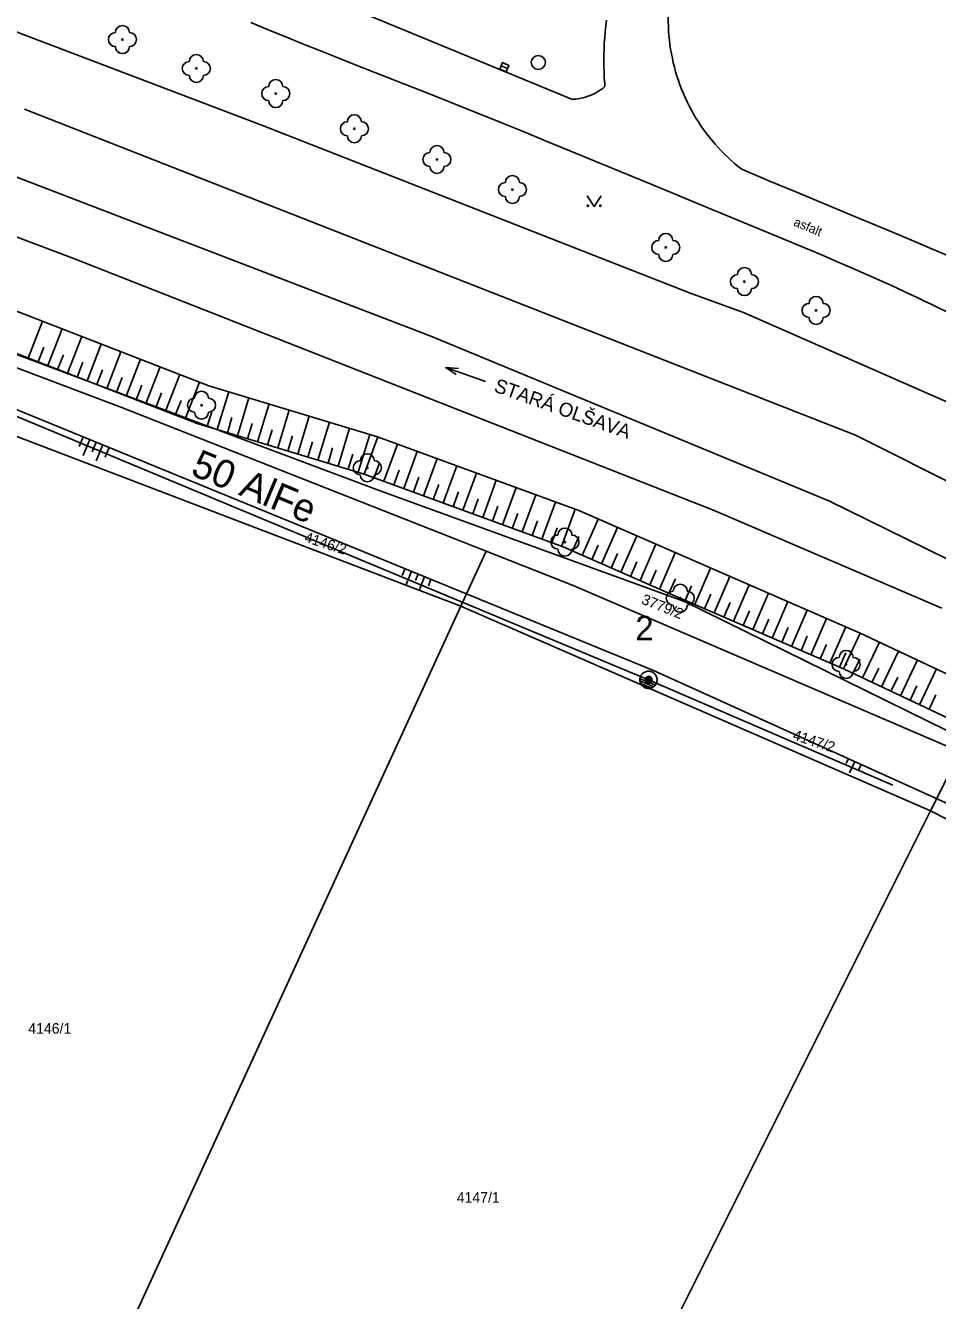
# Model space of a CAD drawing. Extents: x -540150 to -533593, y -1185082 to -1180066.
# Drawn here: x -536338.1 to -536273, y -1184826.1 to -1184735.2 of the extents above; entities that cross this region are included whole.
import ezdxf

# ---------------------------------------------------------------- set-up
doc = ezdxf.new("R2010")
doc.units = 0
for name, color, linetype in [('KN_HRAN_K_Ú', 7, 'Continuous'), ('KN_HRAN_PARCEL', 7, 'Continuous'), ('KN_PARC_Č', 7, 'Continuous'), ('Vrstva 10', 7, 'Continuous'), ('Vrstva 13', 7, 'Continuous'), ('Vrstva 14', 7, 'Continuous'), ('Vrstva 15', 7, 'Continuous'), ('Vrstva 2', 7, 'Continuous'), ('Vrstva 22', 7, 'Continuous'), ('Vrstva 25', 7, 'Continuous'), ('Vrstva 27', 7, 'Continuous'), ('Vrstva 36', 7, 'Continuous'), ('Vrstva 40', 7, 'Continuous'), ('Vrstva 45', 7, 'Continuous'), ('Vrstva 52', 7, 'Continuous'), ('Vrstva 53', 7, 'Continuous'), ('Vrstva 7', 7, 'Continuous')]:
    doc.layers.add(name, color=color, linetype=linetype)

# ---------------------------------------------------------------- blocks, each defined once
blk = doc.blocks.new('VN440')
at = {"layer": 'Vrstva 2'}
for points in [[(1.22, 0), (1.21, 0.13), (1.19, 0.25), (1.16, 0.38), (1.11, 0.5), (1.05, 0.61), (0.98, 0.72), (0.9, 0.82), (0.81, 0.91), (0.71, 0.99), (0.6, 1.06), (0.49, 1.12), (0.37, 1.16), (0.25, 1.2), (0.12, 1.22), (-0.01, 1.22), (-0.14, 1.22), (-0.26, 1.2), (-0.39, 1.16), (-0.51, 1.12), (-0.62, 1.06), (-0.73, 0.99), (-0.83, 0.91), (-0.92, 0.82), (-1, 0.72), (-1.07, 0.61), (-1.13, 0.5), (-1.18, 0.38), (-1.21, 0.25), (-1.23, 0.13), (-1.24, 0), (-1.23, -0.13), (-1.21, -0.26), (-1.18, -0.38), (-1.13, -0.5), (-1.07, -0.62), (-1, -0.73), (-0.92, -0.83), (-0.83, -0.92), (-0.73, -1), (-0.62, -1.07), (-0.51, -1.13), (-0.39, -1.17), (-0.26, -1.2), (-0.14, -1.23), (-0.01, -1.23), (0.12, -1.23), (0.25, -1.2), (0.37, -1.17), (0.49, -1.13), (0.6, -1.07), (0.71, -1), (0.81, -0.92), (0.9, -0.83), (0.98, -0.73), (1.05, -0.62), (1.11, -0.5), (1.16, -0.38), (1.19, -0.26), (1.21, -0.13), (1.22, 0)], [(-1.24, 0), (1.22, 0)], [(-1.18, -0.34), (1.1, -0.34)], [(-1.01, -0.63), (0.97, -0.63)], [(-0.74, -0.92), (0.68, -0.92)]]:
    blk.add_lwpolyline(points, dxfattribs=at)

msp = doc.modelspace()

# ---------------------------------------------------------------- linework, layer by layer
at = {"layer": 'KN_HRAN_K_Ú'}
for p, q in [((-536356.012, -1184743.741), (-536334.692, -1184751.821)), ((-536334.692, -1184751.821), (-536288.932, -1184769.811)), ((-536288.932, -1184769.811), (-536272.712, -1184776.781))]:
    msp.add_line(p, q, dxfattribs=at)
at = {"layer": 'KN_HRAN_PARCEL'}
for p, q in [((-536309.152, -1184757.381), (-536365.022, -1184735.941)), ((-536278.862, -1184764.441), (-536338.122, -1184741.201)), ((-536375.042, -1184745.111), (-536312.562, -1184768.481)), ((-536280.772, -1184769.131), (-536309.152, -1184757.381)), ((-536339.442, -1184759.351), (-536331.262, -1184762.451)), ((-536331.262, -1184762.451), (-536305.212, -1184772.721)), ((-536341.152, -1184763.591), (-536307.012, -1184776.641)), ((-536244.672, -1184781.561), (-536278.862, -1184764.441)), ((-536312.562, -1184768.481), (-536291.062, -1184776.301)), ((-536249.882, -1184784.311), (-536280.772, -1184769.131)), ((-536307.012, -1184776.641), (-536305.212, -1184772.721)), ((-536305.212, -1184772.721), (-536298.992, -1184775.171)), ((-536298.992, -1184775.171), (-536271.392, -1184787.031)), ((-536337.992, -1184844.061), (-536307.012, -1184776.641)), ((-536307.012, -1184776.641), (-536273.502, -1184791.241)), ((-536291.062, -1184776.301), (-536256.302, -1184793.401)), ((-536273.502, -1184791.241), (-536271.392, -1184787.031)), ((-536306.452, -1184857.041), (-536273.502, -1184791.241)), ((-536273.502, -1184791.241), (-536252.972, -1184801.691))]:
    msp.add_line(p, q, dxfattribs=at)
at = {"layer": 'Vrstva 10'}
for p, q in [((-536311.657, -1184735.296), (-536324.262, -1184730.101)), ((-536299.052, -1184740.491), (-536311.657, -1184735.296)), ((-536285.045, -1184746.291), (-536286.972, -1184745.481)), ((-536285.075, -1184750.004), (-536290.122, -1184747.921)), ((-536293.262, -1184781.211), (-536349.102, -1184758.351)), ((-536257.372, -1184797.481), (-536293.262, -1184781.211))]:
    msp.add_line(p, q, dxfattribs=at)
for points in [[(-536291.989, -1184737.241), (-536292.044, -1184736.917), (-536292.092, -1184736.592), (-536292.132, -1184736.265), (-536292.164, -1184735.938), (-536292.187, -1184735.61), (-536292.203, -1184735.282), (-536292.211, -1184734.953), (-536292.211, -1184734.624), (-536292.203, -1184734.296), (-536292.187, -1184733.967), (-536292.162, -1184733.639), (-536292.13, -1184733.312), (-536292.09, -1184732.986), (-536292.042, -1184732.66), (-536291.986, -1184732.336), (-536291.923, -1184732.014), (-536291.851, -1184731.693), (-536291.772, -1184731.374), (-536291.684, -1184731.057), (-536291.59, -1184730.742), (-536291.487, -1184730.429), (-536291.432, -1184730.271)], [(-536318.292, -1184736.521), (-536319.2, -1184736.153), (-536320.787, -1184735.503), (-536321.976, -1184735.011)], [(-536296.617, -1184734.851), (-536296.669, -1184735.259), (-536296.713, -1184735.667), (-536296.749, -1184736.077), (-536296.777, -1184736.487)], [(-536309.01, -1184740.205), (-536313.153, -1184738.57), (-536314.707, -1184737.955), (-536316.065, -1184737.414), (-536317.253, -1184736.939), (-536318.292, -1184736.521)], [(-536296.777, -1184736.487), (-536296.798, -1184736.898), (-536296.81, -1184737.309), (-536296.814, -1184737.72), (-536296.81, -1184738.132), (-536296.798, -1184738.543), (-536296.778, -1184738.953), (-536296.75, -1184739.364), (-536296.732, -1184739.581)], [(-536286.972, -1184745.481), (-536287.229, -1184745.277), (-536287.482, -1184745.066), (-536287.729, -1184744.849), (-536287.971, -1184744.626), (-536288.208, -1184744.398), (-536288.438, -1184744.164), (-536288.663, -1184743.924), (-536288.882, -1184743.679), (-536289.096, -1184743.428), (-536289.302, -1184743.173), (-536289.503, -1184742.912), (-536289.697, -1184742.647), (-536289.885, -1184742.377), (-536290.066, -1184742.103), (-536290.241, -1184741.824), (-536290.408, -1184741.541), (-536290.569, -1184741.254), (-536290.722, -1184740.963), (-536290.869, -1184740.669), (-536291.008, -1184740.371), (-536291.14, -1184740.07), (-536291.265, -1184739.766), (-536291.382, -1184739.459), (-536291.492, -1184739.149), (-536291.594, -1184738.836), (-536291.688, -1184738.521), (-536291.775, -1184738.204), (-536291.854, -1184737.885), (-536291.925, -1184737.564), (-536291.989, -1184737.241)], [(-536296.732, -1184739.581), (-536296.869, -1184739.692), (-536297.011, -1184739.796), (-536297.158, -1184739.893), (-536297.309, -1184739.984), (-536297.464, -1184740.068), (-536297.622, -1184740.145), (-536297.784, -1184740.214), (-536297.949, -1184740.276), (-536298.116, -1184740.331), (-536298.286, -1184740.378), (-536298.458, -1184740.417), (-536298.631, -1184740.448), (-536298.806, -1184740.472), (-536298.981, -1184740.487), (-536299.052, -1184740.491)], [(-536305.383, -1184741.646), (-536306.644, -1184741.143), (-536309.01, -1184740.205)], [(-536296.971, -1184745.087), (-536301.082, -1184743.391), (-536302.607, -1184742.766), (-536304.039, -1184742.186), (-536305.383, -1184741.646)], [(-536290.122, -1184747.921), (-536292.861, -1184746.786), (-536296.971, -1184745.087)], [(-536276.681, -1184749.772), (-536279.254, -1184748.7), (-536283.116, -1184747.096), (-536285.045, -1184746.291)], [(-536268.452, -1184753.311), (-536269.601, -1184752.801), (-536270.679, -1184752.329), (-536271.692, -1184751.889), (-536272.644, -1184751.48), (-536273.536, -1184751.098), (-536275.212, -1184750.389), (-536276.681, -1184749.772)], [(-536281.34, -1184751.564), (-536282.435, -1184751.103), (-536283.394, -1184750.701), (-536285.075, -1184750.004)], [(-536272.343, -1184755.642), (-536272.888, -1184755.375), (-536273.416, -1184755.119), (-536273.929, -1184754.873), (-536274.427, -1184754.637), (-536275.395, -1184754.186), (-536276.304, -1184753.769), (-536277.159, -1184753.383), (-536277.962, -1184753.025), (-536278.717, -1184752.693), (-536279.425, -1184752.385), (-536280.09, -1184752.098), (-536281.34, -1184751.564)]]:
    msp.add_lwpolyline(points, dxfattribs=at)
at = {"layer": 'Vrstva 14'}
for p, q in [((-536364.873, -1184745.447), (-536324.985, -1184760.916)), ((-536365.832, -1184748.091), (-536325.812, -1184763.611)), ((-536324.985, -1184760.916), (-536312.943, -1184764.556)), ((-536325.812, -1184763.611), (-536313.902, -1184767.211)), ((-536312.943, -1184764.556), (-536298.603, -1184769.815)), ((-536313.902, -1184767.211), (-536299.722, -1184772.411)), ((-536298.603, -1184769.815), (-536290.426, -1184773.389)), ((-536299.722, -1184772.411), (-536291.692, -1184775.921)), ((-536290.426, -1184773.389), (-536278.525, -1184778.549)), ((-536291.692, -1184775.921), (-536279.722, -1184781.111)), ((-536278.525, -1184778.549), (-536265.708, -1184784.588)), ((-536279.722, -1184781.111), (-536267.072, -1184787.071))]:
    msp.add_line(p, q, dxfattribs=at)
at = {"layer": 'Vrstva 15'}
for p, q in [((-536337.862, -1184758.938), (-536336.845, -1184756.317)), ((-536336.463, -1184759.48), (-536335.446, -1184756.859)), ((-536335.065, -1184760.023), (-536334.048, -1184757.401)), ((-536333.666, -1184760.565), (-536332.649, -1184757.944)), ((-536337.162, -1184759.209), (-536336.756, -1184758.161)), ((-536335.764, -1184759.752), (-536335.357, -1184758.703)), ((-536332.268, -1184761.107), (-536331.251, -1184758.486)), ((-536334.365, -1184760.294), (-536333.959, -1184759.245)), ((-536332.967, -1184760.836), (-536332.56, -1184759.788)), ((-536330.869, -1184761.65), (-536329.852, -1184759.028)), ((-536329.471, -1184762.192), (-536328.454, -1184759.571)), ((-536331.568, -1184761.379), (-536331.162, -1184760.33)), ((-536328.072, -1184762.735), (-536327.055, -1184760.113)), ((-536326.673, -1184763.277), (-536325.657, -1184760.655)), ((-536330.17, -1184761.921), (-536329.763, -1184760.872)), ((-536328.771, -1184762.463), (-536328.365, -1184761.415)), ((-536324.376, -1184764.045), (-536323.56, -1184761.347)), ((-536327.373, -1184763.006), (-536326.966, -1184761.957)), ((-536322.94, -1184764.479), (-536322.124, -1184761.781)), ((-536321.504, -1184764.913), (-536320.689, -1184762.215)), ((-536325.094, -1184763.828), (-536324.768, -1184762.749)), ((-536323.658, -1184764.262), (-536323.332, -1184763.183)), ((-536320.069, -1184765.347), (-536319.253, -1184762.649)), ((-536318.633, -1184765.781), (-536317.817, -1184763.083)), ((-536317.197, -1184766.215), (-536316.381, -1184763.517)), ((-536322.222, -1184764.696), (-536321.896, -1184763.617)), ((-536320.787, -1184765.13), (-536320.46, -1184764.051)), ((-536315.761, -1184766.649), (-536314.945, -1184763.951)), ((-536314.325, -1184767.083), (-536313.509, -1184764.385)), ((-536333.936, -1184764.56), (-536334.219, -1184765.245)), ((-536333.473, -1184764.749), (-536333.949, -1184765.898)), ((-536333.01, -1184764.939), (-536333.296, -1184765.628)), ((-536332.547, -1184765.128), (-536333.025, -1184766.281)), ((-536332.084, -1184765.318), (-536332.372, -1184766.011)), ((-536319.351, -1184765.564), (-536319.025, -1184764.485)), ((-536317.915, -1184765.998), (-536317.589, -1184764.919)), ((-536316.479, -1184766.432), (-536316.153, -1184765.353)), ((-536313.902, -1184767.211), (-536312.93, -1184764.561)), ((-536312.494, -1184767.727), (-536311.522, -1184765.077)), ((-536315.043, -1184766.866), (-536314.717, -1184765.787)), ((-536311.085, -1184768.244), (-536310.114, -1184765.594)), ((-536309.677, -1184768.76), (-536308.706, -1184766.11)), ((-536313.198, -1184767.469), (-536312.809, -1184766.409)), ((-536311.79, -1184767.986), (-536311.401, -1184766.926)), ((-536308.269, -1184769.277), (-536307.297, -1184766.627)), ((-536306.861, -1184769.793), (-536305.889, -1184767.143)), ((-536310.381, -1184768.502), (-536309.993, -1184767.442)), ((-536308.973, -1184769.019), (-536308.584, -1184767.958)), ((-536305.452, -1184770.31), (-536304.481, -1184767.659)), ((-536307.565, -1184769.535), (-536307.176, -1184768.475)), ((-536306.156, -1184770.051), (-536305.768, -1184768.991)), ((-536304.044, -1184770.826), (-536303.072, -1184768.176)), ((-536302.636, -1184771.343), (-536301.664, -1184768.693)), ((-536304.748, -1184770.568), (-536304.359, -1184769.508)), ((-536301.227, -1184771.859), (-536300.256, -1184769.209)), ((-536299.819, -1184772.375), (-536298.848, -1184769.725)), ((-536303.34, -1184771.084), (-536302.951, -1184770.024)), ((-536301.932, -1184771.601), (-536301.543, -1184770.541)), ((-536298.348, -1184773.012), (-536297.215, -1184770.422)), ((-536300.523, -1184772.117), (-536300.135, -1184771.057)), ((-536299.035, -1184772.711), (-536298.582, -1184771.675)), ((-536296.973, -1184773.613), (-536295.841, -1184771.022)), ((-536295.599, -1184774.213), (-536294.466, -1184771.623)), ((-536297.66, -1184773.312), (-536297.208, -1184772.276)), ((-536294.224, -1184774.814), (-536293.092, -1184772.224)), ((-536296.286, -1184773.913), (-536295.833, -1184772.877)), ((-536294.911, -1184774.514), (-536294.459, -1184773.478)), ((-536292.85, -1184775.415), (-536291.717, -1184772.825)), ((-536310.989, -1184773.954), (-536311.182, -1184774.452)), ((-536310.526, -1184774.143), (-536310.897, -1184775.099)), ((-536310.063, -1184774.333), (-536310.25, -1184774.814)), ((-536293.537, -1184775.115), (-536293.084, -1184774.078)), ((-536290.316, -1184776.518), (-536289.192, -1184773.924)), ((-536309.6, -1184774.522), (-536309.965, -1184775.461)), ((-536309.138, -1184774.712), (-536309.318, -1184775.176)), ((-536292.163, -1184775.715), (-536291.71, -1184774.679)), ((-536291.004, -1184776.219), (-536290.554, -1184775.182)), ((-536288.94, -1184777.114), (-536287.815, -1184774.521)), ((-536287.563, -1184777.711), (-536286.439, -1184775.118)), ((-536289.628, -1184776.816), (-536289.178, -1184775.779)), ((-536286.187, -1184778.308), (-536285.062, -1184775.714)), ((-536288.251, -1184777.413), (-536287.802, -1184776.375)), ((-536286.875, -1184778.009), (-536286.425, -1184776.972)), ((-536284.811, -1184778.905), (-536283.687, -1184776.311)), ((-536283.435, -1184779.501), (-536282.311, -1184776.908)), ((-536285.499, -1184778.606), (-536285.049, -1184777.569)), ((-536282.059, -1184780.098), (-536280.934, -1184777.504)), ((-536284.123, -1184779.203), (-536283.673, -1184778.165)), ((-536282.747, -1184779.8), (-536282.297, -1184778.762)), ((-536280.682, -1184780.695), (-536279.558, -1184778.101)), ((-536279.722, -1184781.111), (-536278.517, -1184778.553)), ((-536281.37, -1184780.396), (-536280.92, -1184779.359)), ((-536278.365, -1184781.75), (-536277.16, -1184779.192)), ((-536277.008, -1184782.39), (-536275.803, -1184779.832)), ((-536279.994, -1184780.993), (-536279.544, -1184779.956)), ((-536279.044, -1184781.431), (-536278.561, -1184780.407)), ((-536275.651, -1184783.029), (-536274.446, -1184780.471)), ((-536277.687, -1184782.07), (-536277.204, -1184781.047)), ((-536276.33, -1184782.709), (-536275.848, -1184781.686)), ((-536274.294, -1184783.668), (-536273.089, -1184781.11)), ((-536274.973, -1184783.349), (-536274.491, -1184782.325)), ((-536273.616, -1184783.988), (-536273.134, -1184782.965)), ((-536279.368, -1184787.509), (-536279.532, -1184787.865)), ((-536278.913, -1184787.716), (-536279.288, -1184788.529)), ((-536278.457, -1184787.922), (-536278.624, -1184788.284))]:
    msp.add_line(p, q, dxfattribs=at)
at = {"layer": 'Vrstva 22'}
for centre in [(-536331.142, -1184736.231), (-536325.872, -1184738.291), (-536320.212, -1184740.081), (-536314.602, -1184742.591), (-536308.712, -1184744.781), (-536303.332, -1184746.921), (-536292.392, -1184751.051), (-536286.782, -1184753.491), (-536281.672, -1184755.541), (-536325.502, -1184762.301), (-536313.678, -1184766.764), (-536299.584, -1184772.062), (-536291.36, -1184776.066), (-536279.53, -1184780.789)]:
    msp.add_circle(centre, 0.05, dxfattribs=at)
for centre, start, end in [((-536331.142, -1184735.731), 0, 180), ((-536331.642, -1184736.231), 90, 270), ((-536330.642, -1184736.231), 270, 90), ((-536331.142, -1184736.731), 180, 0), ((-536326.372, -1184738.291), 90, 270), ((-536325.872, -1184737.791), 0, 180), ((-536325.372, -1184738.291), 270, 90), ((-536325.872, -1184738.791), 180, 0), ((-536320.712, -1184740.081), 90, 270), ((-536320.212, -1184739.581), 0, 180), ((-536319.712, -1184740.081), 270, 90), ((-536320.212, -1184740.581), 180, 0), ((-536314.602, -1184742.091), 0, 180), ((-536315.102, -1184742.591), 90, 270), ((-536314.102, -1184742.591), 270, 90), ((-536314.602, -1184743.091), 180, 0), ((-536309.212, -1184744.781), 90, 270), ((-536308.712, -1184744.281), 0, 180), ((-536308.212, -1184744.781), 270, 90), ((-536308.712, -1184745.281), 180, 0), ((-536303.332, -1184746.421), 0, 180), ((-536303.832, -1184746.921), 90, 270), ((-536302.832, -1184746.921), 270, 90), ((-536303.332, -1184747.421), 180, 0), ((-536292.892, -1184751.051), 90, 270), ((-536292.392, -1184750.551), 0, 180), ((-536291.892, -1184751.051), 270, 90), ((-536292.392, -1184751.551), 180, 0), ((-536286.782, -1184752.991), 0, 180), ((-536287.282, -1184753.491), 90, 270), ((-536286.282, -1184753.491), 270, 90), ((-536286.782, -1184753.991), 180, 0), ((-536282.172, -1184755.541), 90, 270), ((-536281.672, -1184755.041), 0, 180), ((-536281.172, -1184755.541), 270, 90), ((-536281.672, -1184756.041), 180, 0), ((-536325.502, -1184761.801), 0, 180), ((-536326.002, -1184762.301), 90, 270), ((-536325.002, -1184762.301), 270, 90), ((-536325.502, -1184762.801), 180, 0), ((-536314.178, -1184766.764), 90, 270), ((-536313.678, -1184766.264), 0, 180), ((-536313.178, -1184766.764), 270, 90), ((-536313.678, -1184767.264), 180, 0), ((-536300.084, -1184772.062), 90, 270), ((-536299.584, -1184771.562), 0, 180), ((-536299.084, -1184772.062), 270, 90), ((-536299.584, -1184772.562), 180, 0), ((-536291.36, -1184775.566), 0, 180), ((-536291.86, -1184776.066), 90, 270), ((-536290.86, -1184776.066), 270, 90), ((-536291.36, -1184776.566), 180, 0), ((-536279.53, -1184780.289), 0, 180), ((-536280.03, -1184780.789), 90, 270), ((-536279.03, -1184780.789), 270, 90), ((-536279.53, -1184781.289), 180, 0)]:
    msp.add_arc(centre, 0.5, start, end, dxfattribs=at)
at = {"layer": 'Vrstva 25'}
for radius in [0.25, 0.2, 0.15, 0.1, 0.05]:
    msp.add_circle((-536293.619, -1184781.887), radius, dxfattribs=at)
at = {"layer": 'Vrstva 27'}
msp.add_line((-536304.132, -1184738.103), (-536303.672, -1184738.299), dxfattribs=at)
msp.add_lwpolyline([(-536304.23, -1184738.333), (-536303.77, -1184738.529), (-536303.574, -1184738.069), (-536304.034, -1184737.873)], close=True, dxfattribs=at)
msp.add_circle((-536301.482, -1184737.861), 0.5, dxfattribs=at)
at = {"layer": 'Vrstva 36'}
msp.add_lwpolyline([(-536297.998, -1184747.384), (-536297.498, -1184748.134), (-536296.998, -1184747.384)], dxfattribs=at)
for centre in [(-536297.948, -1184748.083), (-536297.049, -1184748.083)]:
    msp.add_circle(centre, 0.05, dxfattribs=at)
at = {"layer": 'Vrstva 45'}
msp.add_line((-536305.26, -1184760.603), (-536308.088, -1184759.603), dxfattribs=at)
msp.add_lwpolyline([(-536307.339, -1184760.112), (-536308.088, -1184759.603), (-536307.185, -1184759.678)], dxfattribs=at)
at = {"layer": 'Vrstva 52'}
msp.add_lwpolyline([(-536349.187, -1184758.726), (-536293.618, -1184781.887), (-536276.193, -1184789.391)], dxfattribs=at)
at = {"layer": 'Vrstva 7'}
for p, q in [((-536286.842, -1184755.701), (-536290.592, -1184754.341)), ((-536265.082, -1184765.271), (-536286.842, -1184755.701))]:
    msp.add_line(p, q, dxfattribs=at)
for points in [[(-536321.262, -1184742.311), (-536339.347, -1184735.45)], [(-536290.592, -1184754.341), (-536321.262, -1184742.311)]]:
    msp.add_lwpolyline(points, dxfattribs=at)

# ---------------------------------------------------------------- block references
at = {"layer": 'Vrstva 13', "xscale": 0.5, "yscale": 0.5000000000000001, "rotation": -22.62591945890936}
msp.add_blockref('VN440', (-536293.619, -1184781.886), dxfattribs=at)

# ---------------------------------------------------------------- texts
at = {"layer": 'KN_PARC_Č'}
for s, rotation, p in [('4146/2', 342, (-536318.229, -1184772.026)), ('3779/2', 338.2639, (-536294.183, -1184776.436)), ('4147/2', 342, (-536283.387, -1184786.133))]:
    msp.add_text(s, height=0.75, rotation=rotation, dxfattribs=at).set_placement(p)
for s, p in [('4146/1', (-536337.861, -1184807.121)), ('4147/1', (-536307.301, -1184819.171))]:
    msp.add_text(s, height=0.75, dxfattribs=at).set_placement(p)
at = {"layer": 'Vrstva 14'}
msp.add_text('2', height=1.75, dxfattribs=at).set_placement((-536294.563, -1184779.073))
at = {"layer": 'Vrstva 40'}
msp.add_text('asfalt', height=0.65, rotation=337.46643, dxfattribs=at).set_placement((-536283.331, -1184749.474))
at = {"layer": 'Vrstva 45'}
msp.add_text('STARÁ OLŠAVA', height=1, rotation=340.53243, dxfattribs=at).set_placement((-536304.713, -1184761.315))
at = {"layer": 'Vrstva 53'}
msp.add_text('50 AlFe', height=2, rotation=337.374, dxfattribs=at).set_placement((-536326.36, -1184767.246))

doc.saveas('drawing.dxf')
